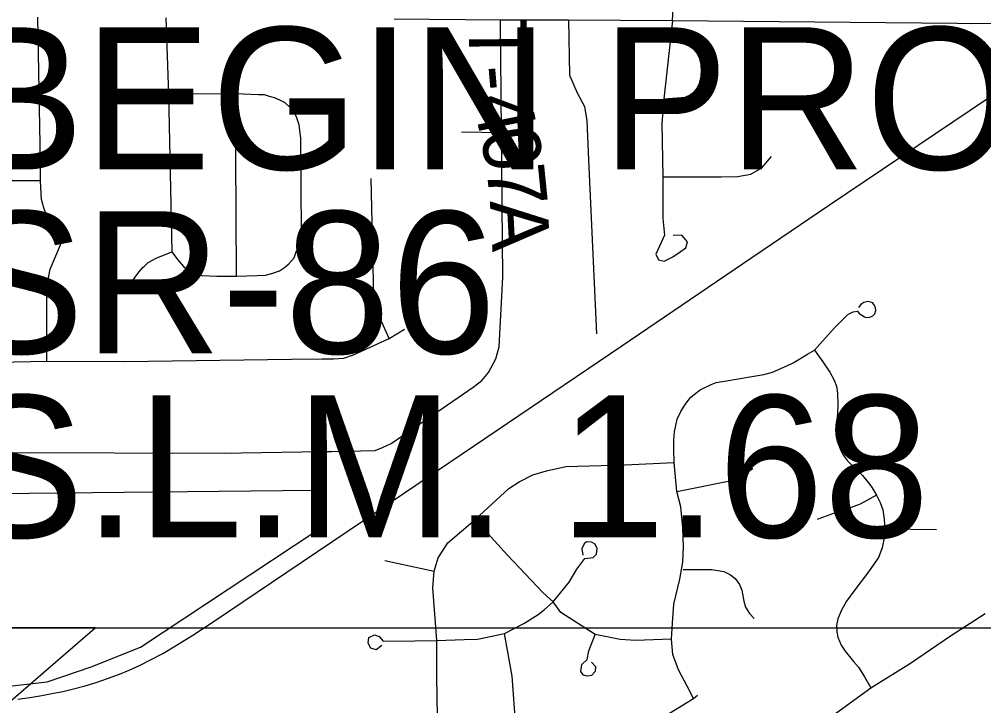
# Model space of a CAD drawing. Extents: x -59 to 82, y -3 to 49.
# Drawn here: x -52.032 to -51.082, y 45.657 to 46.333 of the extents above; entities that cross this region are included whole.
import ezdxf

# ---------------------------------------------------------------- set-up
doc = ezdxf.new("R2010")
doc.units = 0
for name, color, linetype in [('GM_X_Corporation', 7, 'Continuous'), ('GM_X_County_Road', 7, 'Continuous'), ('GM_X_Rail_Line', 7, 'Continuous'), ('GM_X_State_Route', 7, 'Continuous'), ('GM_X_Township_Road', 7, 'Continuous'), ('GM_X_Township_Road_Text', 7, 'Continuous'), ('SH_Data', 7, 'Continuous')]:
    doc.layers.add(name, color=color, linetype=linetype)

msp = doc.modelspace()

# ---------------------------------------------------------------- linework, layer by layer
at = {"layer": 'GM_X_Corporation'}
for p, q in [((-51.74184, 45.86879), (-52.17362, 45.86436)), ((-51.74013, 45.82901), (-51.74184, 45.86879)), ((-51.91266, 45.71459), (-51.74013, 45.82901)), ((-51.9614, 45.69524), (-51.91266, 45.71459)), ((-52.00458, 45.68057), (-51.9614, 45.69524)), ((-52.07026, 45.67296), (-52.00458, 45.68057))]:
    msp.add_line(p, q, dxfattribs=at)
at = {"layer": 'GM_X_County_Road'}
for p, q in [((-51.38874, 46.33189), (-51.37852, 46.54397)), ((-51.66282, 46.33339), (-51.55826, 46.33237)), ((-51.55826, 46.33237), (-51.49116, 46.3325)), ((-51.49116, 46.3325), (-51.38874, 46.33189)), ((-51.38874, 46.33189), (-51.07358, 46.32889))]:
    msp.add_line(p, q, dxfattribs=at)
at = {"layer": 'GM_X_Rail_Line'}
for p, q in [((-51.23431, 46.15016), (-50.91171, 46.36748)), ((-51.32004, 46.09199), (-51.23431, 46.15016)), ((-51.43888, 46.01143), (-51.32004, 46.09199)), ((-51.66397, 45.85914), (-51.43888, 46.01143)), ((-51.82794, 45.74852), (-51.66397, 45.85914)), ((-51.84409, 45.73754), (-51.82794, 45.74852)), ((-51.86113, 45.72657), (-51.84409, 45.73754)), ((-51.87656, 45.71684), (-51.86113, 45.72657)), ((-51.89075, 45.70828), (-51.87656, 45.71684)), ((-51.91323, 45.69704), (-51.90342, 45.70168)), ((-51.90342, 45.70168), (-51.89075, 45.70828)), ((-51.93357, 45.68803), (-51.92394, 45.69213)), ((-51.92394, 45.69213), (-51.91323, 45.69704)), ((-51.9565, 45.67982), (-51.94526, 45.68375)), ((-51.94526, 45.68375), (-51.93357, 45.68803)), ((-51.98924, 45.67108), (-51.97862, 45.67349)), ((-51.97862, 45.67349), (-51.96738, 45.67652)), ((-51.96738, 45.67652), (-51.9565, 45.67982)), ((-52.0334, 45.66341), (-52.02162, 45.6651)), ((-52.02162, 45.6651), (-52.00994, 45.66697)), ((-52.00994, 45.66697), (-51.99843, 45.6692)), ((-51.99843, 45.6692), (-51.98924, 45.67108))]:
    msp.add_line(p, q, dxfattribs=at)
at = {"layer": 'GM_X_State_Route'}
for p, q in [((-51.11513, 45.72586), (-51.08096, 45.74788)), ((-51.15458, 45.69901), (-51.11513, 45.72586)), ((-51.19343, 45.67462), (-51.15458, 45.69901)), ((-51.2393, 45.64149), (-51.19343, 45.67462))]:
    msp.add_line(p, q, dxfattribs=at)
at = {"layer": 'GM_X_Township_Road'}
for p, q in [((-52.01158, 46.20964), (-52.01375, 46.33501)), ((-51.88775, 46.33445), (-51.8853, 46.25905)), ((-51.55726, 46.22134), (-51.55826, 46.33237)), ((-51.49116, 46.3325), (-51.49037, 46.27788)), ((-51.38874, 46.33189), (-51.39744, 46.25475)), ((-51.49037, 46.27788), (-51.48288, 46.2605)), ((-51.37037, 46.25969), (-51.36626, 46.26183)), ((-51.36626, 46.26183), (-51.36108, 46.2619)), ((-51.36108, 46.2619), (-51.35797, 46.26091)), ((-51.8853, 46.25905), (-51.88184, 46.1039)), ((-51.81917, 46.25958), (-51.88249, 46.25907)), ((-51.81825, 46.08008), (-51.81917, 46.25958)), ((-51.79655, 46.25866), (-51.81917, 46.25958)), ((-51.79049, 46.2584), (-51.79655, 46.25866)), ((-51.78563, 46.25705), (-51.79049, 46.2584)), ((-51.78077, 46.2557), (-51.78563, 46.25705)), ((-51.77556, 46.25318), (-51.78077, 46.2557)), ((-51.77035, 46.25067), (-51.77556, 46.25318)), ((-51.48288, 46.2605), (-51.47545, 46.24721)), ((-51.39744, 46.25475), (-51.39925, 46.23043)), ((-51.39744, 46.25475), (-51.37136, 46.25658)), ((-51.37136, 46.25658), (-51.37037, 46.25969)), ((-51.36816, 46.24944), (-51.3713, 46.25243)), ((-51.35797, 46.26091), (-51.35582, 46.25576)), ((-51.35582, 46.25576), (-51.3568, 46.25167)), ((-51.76512, 46.24591), (-51.77035, 46.25067)), ((-51.76207, 46.24312), (-51.76512, 46.24591)), ((-51.7588, 46.23592), (-51.76207, 46.24312)), ((-51.47545, 46.24721), (-51.47317, 46.23281)), ((-51.364, 46.24846), (-51.36816, 46.24944)), ((-51.35884, 46.24957), (-51.364, 46.24846)), ((-51.3568, 46.25167), (-51.35884, 46.24957)), ((-51.75659, 46.22904), (-51.7588, 46.23592)), ((-51.755, 46.21545), (-51.75659, 46.22904)), ((-51.47317, 46.23281), (-51.47146, 46.19468)), ((-51.39925, 46.23043), (-51.39831, 46.17772)), ((-51.75414, 46.12276), (-51.755, 46.21545)), ((-51.59676, 46.22207), (-51.55726, 46.22134)), ((-51.55596, 46.07911), (-51.55726, 46.22134)), ((-52.01118, 46.17416), (-52.01158, 46.20964)), ((-51.30097, 46.1866), (-51.29128, 46.19791)), ((-51.47146, 46.19468), (-51.46375, 46.02316)), ((-51.31188, 46.18054), (-51.30097, 46.1866)), ((-51.39831, 46.17772), (-51.39831, 46.13692)), ((-51.39831, 46.17772), (-51.34055, 46.17772)), ((-51.34055, 46.17772), (-51.3248, 46.17812)), ((-51.3248, 46.17812), (-51.31188, 46.18054)), ((-52.06148, 46.17414), (-52.01118, 46.17416)), ((-52.01083, 46.16682), (-52.01118, 46.17416)), ((-51.68303, 46.06033), (-51.68564, 46.17604)), ((-52.0103, 46.15553), (-52.01083, 46.16682)), ((-52.0074, 46.145), (-52.0103, 46.15553)), ((-52.00138, 46.13459), (-52.0074, 46.145)), ((-51.99591, 46.12928), (-52.00138, 46.13459)), ((-51.98905, 46.12419), (-51.99591, 46.12928)), ((-51.39831, 46.13692), (-51.3967, 46.12036)), ((-51.98951, 46.11825), (-51.98905, 46.12419)), ((-51.98518, 46.12219), (-51.98905, 46.12419)), ((-51.98232, 46.12087), (-51.98518, 46.12219)), ((-51.75679, 46.11032), (-51.75414, 46.12276)), ((-51.3967, 46.12036), (-51.40154, 46.10946)), ((-51.37973, 46.12036), (-51.38821, 46.11996)), ((-51.37408, 46.1139), (-51.37973, 46.12036)), ((-52.00182, 46.08685), (-51.99045, 46.11319)), ((-51.99045, 46.11319), (-51.98951, 46.11825)), ((-51.75942, 46.1039), (-51.75679, 46.11032)), ((-51.37569, 46.10784), (-51.37408, 46.1139)), ((-51.89728, 46.09783), (-51.88184, 46.1039)), ((-51.88184, 46.1039), (-51.87624, 46.09635)), ((-51.76156, 46.09816), (-51.75942, 46.1039)), ((-51.40154, 46.10946), (-51.40518, 46.10179)), ((-51.40518, 46.10179), (-51.40275, 46.09613)), ((-51.38862, 46.09896), (-51.38135, 46.10381)), ((-51.38135, 46.10381), (-51.37569, 46.10784)), ((-51.90927, 46.08959), (-51.90517, 46.09355)), ((-51.90517, 46.09355), (-51.89728, 46.09783)), ((-51.87624, 46.09635), (-51.87033, 46.08945)), ((-51.77109, 46.08846), (-51.76681, 46.09207)), ((-51.76681, 46.09207), (-51.76156, 46.09816)), ((-51.40275, 46.09613), (-51.3971, 46.09492)), ((-51.3971, 46.09492), (-51.38862, 46.09896)), ((-52.00403, 46.07473), (-52.00182, 46.08685)), ((-51.928, 46.06546), (-51.91453, 46.08386)), ((-51.91453, 46.08386), (-51.9101, 46.08879)), ((-51.9101, 46.08879), (-51.90927, 46.08959)), ((-51.87033, 46.08945), (-51.86425, 46.08452)), ((-51.86425, 46.08452), (-51.85834, 46.08274)), ((-51.85834, 46.08274), (-51.85231, 46.08061)), ((-51.78982, 46.08107), (-51.78242, 46.08288)), ((-51.78242, 46.08288), (-51.77585, 46.08534)), ((-51.77585, 46.08534), (-51.77109, 46.08846)), ((-52.00491, 46.0613), (-52.00403, 46.07473)), ((-51.85231, 46.08061), (-51.83763, 46.08008)), ((-51.83763, 46.08008), (-51.81825, 46.08008)), ((-51.81825, 46.08008), (-51.79787, 46.08057)), ((-51.79787, 46.08057), (-51.78982, 46.08107)), ((-51.55945, 46.01041), (-51.55596, 46.07911)), ((-52.00513, 45.99618), (-52.00491, 46.0613)), ((-51.68186, 46.05078), (-51.68303, 46.06033)), ((-51.20048, 46.05415), (-51.2033, 46.05224)), ((-51.19625, 46.0549), (-51.20048, 46.05415)), ((-51.19168, 46.05386), (-51.19625, 46.0549)), ((-51.19049, 46.05215), (-51.19168, 46.05386)), ((-51.6797, 46.04487), (-51.68186, 46.05078)), ((-51.67375, 46.0317), (-51.6797, 46.04487)), ((-51.21609, 46.04218), (-51.2108, 46.04488)), ((-51.2108, 46.04488), (-51.20662, 46.0455)), ((-51.20662, 46.0455), (-51.20519, 46.04317)), ((-51.2033, 46.05224), (-51.20559, 46.04924)), ((-51.18895, 46.04917), (-51.19049, 46.05215)), ((-51.18966, 46.04301), (-51.18867, 46.04614)), ((-51.18867, 46.04614), (-51.18895, 46.04917)), ((-51.22892, 46.0293), (-51.21816, 46.04033)), ((-51.21816, 46.04033), (-51.21609, 46.04218)), ((-51.20519, 46.04317), (-51.19965, 46.03979)), ((-51.19965, 46.03979), (-51.19807, 46.03933)), ((-51.19807, 46.03933), (-51.19453, 46.03956)), ((-51.19453, 46.03956), (-51.19158, 46.04095)), ((-51.19158, 46.04095), (-51.18966, 46.04301)), ((-51.66779, 46.01852), (-51.67375, 46.0317)), ((-51.66779, 46.01852), (-51.65265, 46.02771)), ((-51.24105, 46.01602), (-51.22892, 46.0293)), ((-51.70306, 46.00268), (-51.66779, 46.01852)), ((-51.24918, 46.00717), (-51.24105, 46.01602)), ((-51.56274, 45.99858), (-51.55945, 46.01041)), ((-51.25581, 46.00321), (-51.24918, 46.00717)), ((-51.24918, 46.00717), (-51.24089, 45.99548)), ((-52.20454, 45.993), (-52.00513, 45.99618)), ((-52.00513, 45.99618), (-51.92839, 45.99609)), ((-51.92839, 45.99609), (-51.76391, 45.9981)), ((-51.76391, 45.9981), (-51.73382, 45.99847)), ((-51.73382, 45.99847), (-51.72279, 45.99861)), ((-51.72279, 45.99861), (-51.71248, 45.9993)), ((-51.71248, 45.9993), (-51.70306, 46.00268)), ((-51.56997, 45.98511), (-51.56274, 45.99858)), ((-51.27001, 45.99471), (-51.25581, 46.00321)), ((-51.29027, 45.98558), (-51.27631, 45.99183)), ((-51.27631, 45.99183), (-51.27001, 45.99471)), ((-51.24089, 45.99548), (-51.23391, 45.98556)), ((-51.58508, 45.97065), (-51.57654, 45.97722)), ((-51.57654, 45.97722), (-51.56997, 45.98511)), ((-51.34575, 45.97511), (-51.33558, 45.97697)), ((-51.33558, 45.97697), (-51.31257, 45.98075)), ((-51.31257, 45.98075), (-51.29905, 45.9833)), ((-51.29905, 45.9833), (-51.29027, 45.98558)), ((-51.23391, 45.98556), (-51.22966, 45.97761)), ((-51.22966, 45.97761), (-51.2275, 45.97177)), ((-51.61983, 45.94672), (-51.58508, 45.97065)), ((-51.36602, 45.96477), (-51.36164, 45.96805)), ((-51.36164, 45.96805), (-51.35089, 45.9732)), ((-51.35089, 45.9732), (-51.34575, 45.97511)), ((-51.2275, 45.97177), (-51.22652, 45.96474)), ((-51.37649, 45.95374), (-51.37129, 45.96035)), ((-51.37129, 45.96035), (-51.36602, 45.96477)), ((-51.22652, 45.96474), (-51.22596, 45.95353)), ((-51.38053, 45.94685), (-51.37649, 45.95374)), ((-51.22596, 45.95353), (-51.22623, 45.94437)), ((-51.66577, 45.91534), (-51.61983, 45.94672)), ((-51.38679, 45.92676), (-51.38431, 45.9392)), ((-51.38431, 45.9392), (-51.38053, 45.94685)), ((-51.22623, 45.94437), (-51.22757, 45.93316)), ((-51.22757, 45.93316), (-51.22804, 45.92611)), ((-51.38756, 45.91877), (-51.38679, 45.92676)), ((-51.22804, 45.92611), (-51.22673, 45.91756)), ((-51.68174, 45.90817), (-51.67431, 45.9113)), ((-51.67431, 45.9113), (-51.66577, 45.91534)), ((-51.38762, 45.9095), (-51.38756, 45.91877)), ((-51.22673, 45.91756), (-51.22307, 45.90815)), ((-52.21195, 45.90649), (-51.82361, 45.90579)), ((-51.82361, 45.90579), (-51.81373, 45.90596)), ((-51.81373, 45.90596), (-51.7337, 45.9073)), ((-51.7337, 45.9073), (-51.7247, 45.90745)), ((-51.7247, 45.90745), (-51.68174, 45.90817)), ((-51.38721, 45.8964), (-51.38762, 45.9095)), ((-51.22307, 45.90815), (-51.22062, 45.90348)), ((-51.22062, 45.90348), (-51.2164, 45.89823)), ((-51.51307, 45.88823), (-51.49386, 45.89263)), ((-51.49386, 45.89263), (-51.4358, 45.89424)), ((-51.4358, 45.89424), (-51.38721, 45.8964)), ((-51.38584, 45.88212), (-51.38721, 45.8964)), ((-51.2164, 45.89823), (-51.20884, 45.89056)), ((-51.5399, 45.87742), (-51.52629, 45.88423)), ((-51.52629, 45.88423), (-51.51307, 45.88823)), ((-51.38447, 45.86784), (-51.38584, 45.88212)), ((-51.32546, 45.88105), (-51.30985, 45.89063)), ((-51.20884, 45.89056), (-51.20167, 45.88374)), ((-51.20167, 45.88374), (-51.19463, 45.87499)), ((-51.54991, 45.87102), (-51.5399, 45.87742)), ((-51.38447, 45.86784), (-51.33076, 45.8789)), ((-51.33076, 45.8789), (-51.32546, 45.88105)), ((-51.19463, 45.87499), (-51.19207, 45.8715)), ((-51.58328, 45.84048), (-51.54991, 45.87102)), ((-51.38062, 45.8528), (-51.38447, 45.86784)), ((-51.18808, 45.86444), (-51.20394, 45.85537)), ((-51.19207, 45.8715), (-51.18808, 45.86444)), ((-51.18808, 45.86444), (-51.18445, 45.857)), ((-51.20394, 45.85537), (-51.21901, 45.84974)), ((-51.18445, 45.857), (-51.18185, 45.84993)), ((-51.37852, 45.832), (-51.38062, 45.8528)), ((-51.23232, 45.84571), (-51.24654, 45.84023)), ((-51.21901, 45.84974), (-51.23232, 45.84571)), ((-51.18185, 45.84993), (-51.18034, 45.84072)), ((-51.60996, 45.81737), (-51.58328, 45.84048)), ((-51.5514, 45.80532), (-51.58328, 45.84048)), ((-51.18034, 45.84072), (-51.17989, 45.8312)), ((-51.37812, 45.81342), (-51.37852, 45.832)), ((-51.17989, 45.8312), (-51.18015, 45.82366)), ((-51.17989, 45.8312), (-51.12875, 45.83062)), ((-51.61963, 45.80252), (-51.60996, 45.81737)), ((-51.47586, 45.81638), (-51.47811, 45.81155)), ((-51.47345, 45.81835), (-51.47586, 45.81638)), ((-51.46866, 45.81814), (-51.47345, 45.81835)), ((-51.46493, 45.8162), (-51.46866, 45.81814)), ((-51.46319, 45.81194), (-51.46493, 45.8162)), ((-51.18015, 45.82366), (-51.18237, 45.81244)), ((-51.47811, 45.81155), (-51.47725, 45.80511)), ((-51.46697, 45.80286), (-51.46386, 45.80609)), ((-51.46386, 45.80609), (-51.46319, 45.81194)), ((-51.37852, 45.79848), (-51.37812, 45.81342)), ((-51.18237, 45.81244), (-51.18606, 45.80299)), ((-51.67209, 45.80014), (-51.62367, 45.78959)), ((-51.62367, 45.78959), (-51.61963, 45.80252)), ((-51.51622, 45.76809), (-51.5514, 45.80532)), ((-51.4831, 45.79155), (-51.47519, 45.80202)), ((-51.47519, 45.80202), (-51.46697, 45.80286)), ((-51.38175, 45.78151), (-51.37852, 45.79848)), ((-51.18606, 45.80299), (-51.19586, 45.7889)), ((-51.62488, 45.77304), (-51.62367, 45.78959)), ((-51.49072, 45.77865), (-51.4831, 45.79155)), ((-51.3783, 45.79119), (-51.35015, 45.79104)), ((-51.35015, 45.79104), (-51.33832, 45.78914)), ((-51.33832, 45.78914), (-51.33177, 45.78598)), ((-51.19586, 45.7889), (-51.20924, 45.77096)), ((-51.50635, 45.75937), (-51.49072, 45.77865)), ((-51.38741, 45.75688), (-51.38175, 45.78151)), ((-51.33177, 45.78598), (-51.32712, 45.78222)), ((-51.32712, 45.78222), (-51.32272, 45.77637)), ((-51.6209, 45.72113), (-51.62488, 45.77304)), ((-51.50635, 45.75937), (-51.51622, 45.76809)), ((-51.32272, 45.77637), (-51.32057, 45.77081)), ((-51.32057, 45.77081), (-51.31865, 45.75992)), ((-51.20924, 45.77096), (-51.21737, 45.76006)), ((-51.51499, 45.75186), (-51.50635, 45.75937)), ((-51.49874, 45.74867), (-51.50635, 45.75937)), ((-51.31865, 45.75992), (-51.31681, 45.75408)), ((-51.21737, 45.76006), (-51.22258, 45.75116)), ((-51.52112, 45.74696), (-51.51499, 45.75186)), ((-51.38902, 45.7383), (-51.38741, 45.75688)), ((-51.31681, 45.75408), (-51.31315, 45.74792)), ((-51.22258, 45.75116), (-51.226, 45.7427)), ((-51.53511, 45.7379), (-51.52112, 45.74696)), ((-51.46492, 45.72706), (-51.49874, 45.74867)), ((-51.31315, 45.74792), (-51.30837, 45.74301)), ((-51.226, 45.7427), (-51.22725, 45.73612)), ((-51.55445, 45.72823), (-51.53511, 45.7379)), ((-51.38983, 45.72255), (-51.38902, 45.7383)), ((-51.22725, 45.73612), (-51.22716, 45.72977)), ((-51.68871, 45.71861), (-51.68803, 45.724)), ((-51.68803, 45.724), (-51.68231, 45.7267)), ((-51.68231, 45.7267), (-51.67759, 45.72501)), ((-51.67759, 45.72501), (-51.67389, 45.72063)), ((-51.67389, 45.72063), (-51.64245, 45.721)), ((-51.64245, 45.721), (-51.6209, 45.72113)), ((-51.621, 45.6856), (-51.6209, 45.72113)), ((-51.6209, 45.72113), (-51.59389, 45.72208)), ((-51.59389, 45.72208), (-51.58097, 45.72253)), ((-51.58097, 45.72253), (-51.55445, 45.72823)), ((-51.54671, 45.68601), (-51.55445, 45.72823)), ((-51.47137, 45.71093), (-51.46492, 45.72706)), ((-51.44027, 45.72227), (-51.46492, 45.72706)), ((-51.4252, 45.72114), (-51.44027, 45.72227)), ((-51.38983, 45.72255), (-51.4252, 45.72114)), ((-51.38841, 45.70741), (-51.38983, 45.72255)), ((-51.22716, 45.72977), (-51.22589, 45.72458)), ((-51.22589, 45.72458), (-51.22271, 45.71668)), ((-51.68601, 45.71356), (-51.68871, 45.71861)), ((-51.68062, 45.71188), (-51.68601, 45.71356)), ((-51.67523, 45.71625), (-51.68062, 45.71188)), ((-51.22271, 45.71668), (-51.21884, 45.71065)), ((-51.47811, 45.69745), (-51.47284, 45.70243)), ((-51.47284, 45.70243), (-51.47137, 45.71093)), ((-51.38285, 45.69217), (-51.38841, 45.70741)), ((-51.21884, 45.71065), (-51.21077, 45.70052)), ((-51.479, 45.69071), (-51.47811, 45.69745)), ((-51.46874, 45.69979), (-51.46463, 45.69569)), ((-51.46463, 45.69569), (-51.46492, 45.69071)), ((-51.37434, 45.67634), (-51.38285, 45.69217)), ((-51.21077, 45.70052), (-51.20577, 45.69481)), ((-51.20577, 45.69481), (-51.19965, 45.68546)), ((-51.62033, 45.64586), (-51.621, 45.6856)), ((-51.54349, 45.64116), (-51.54671, 45.68601)), ((-51.47636, 45.68719), (-51.479, 45.69071)), ((-51.47284, 45.68601), (-51.47636, 45.68719)), ((-51.46874, 45.6866), (-51.47284, 45.68601)), ((-51.46492, 45.69071), (-51.46874, 45.6866)), ((-51.19965, 45.68546), (-51.19343, 45.67462)), ((-51.36819, 45.66403), (-51.37434, 45.67634)), ((-51.43678, 45.62241), (-51.36819, 45.66403)), ((-51.36819, 45.66403), (-51.36409, 45.66726))]:
    msp.add_line(p, q, dxfattribs=at)
at = {"layer": 'SH_Data'}
for points in [[(-52.16577, 45.73353), (-50.40823, 45.73353), (-50.40823, 46.42698), (-52.16577, 46.42698)], [(-52.16577, 45.73353), (-50.40823, 45.73353), (-50.40823, 46.42698), (-52.16577, 46.42698)], [(-52.16577, 45.73353), (-52.77583, 45.02571), (-51.95731, 45.73353)]]:
    msp.add_lwpolyline(points, close=True, dxfattribs=at)

# ---------------------------------------------------------------- texts
at = {"layer": 'GM_X_Township_Road_Text'}
for s, rotation, p in [('T', 270.51428, (-51.58939, 46.33277)), ('-', 274.68471, (-51.5888, 46.28576)), ('4', 281.54833, (-51.58585, 46.25515)), ('0', 281.28239, (-51.57886, 46.22092)), ('7', 275.77067, (-51.57223, 46.18803)), ('A', 273.01031, (-51.56876, 46.15393))]:
    msp.add_text(s, height=0.05682, rotation=rotation, dxfattribs=at).set_placement(p)
at = {"layer": 'SH_Data'}
for s, p in [('BEGIN PROJECT', (-52.09313, 46.18503)), ('SR-86', (-52.09313, 46.00384)), ('S.L.M. 1.68', (-52.09313, 45.82265))]:
    msp.add_text(s, height=0.14, dxfattribs=at).set_placement(p)

doc.saveas('drawing.dxf')
